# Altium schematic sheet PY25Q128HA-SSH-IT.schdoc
size 127 x 101 mm
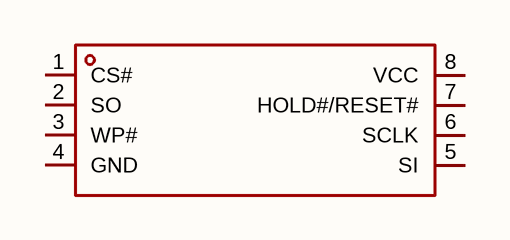
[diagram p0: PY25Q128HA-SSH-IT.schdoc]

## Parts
U?  py25q128ha-ssh-it  [SOP-8_L4.9-W3.9-P1.27-LS6.0-BL]  (value not drawn)

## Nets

Not connected (* = marked no-connect by the designer): U? 1(CS#) 2(SO) 3(WP#) 4(GND) 5(SI) 6(SCLK) 7(HOLD#/RESET#) 8(VCC)

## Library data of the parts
U? = py25q128ha-ssh-it: 接口类型:SPI;存储容量:128Mbit;时钟频率(fc):133MHz;; Manufacturer: PUYA(普冉); AddInBom: yes; ModelId: 75c24a7891ee4dd6bdac16a7163ff87e; ModelName: SOP-8_L4.9-W3.9-P1.27-LS6.0-BL-1; ModelTransform: 192.913,236.22,0,0,0,0,-0.393,2.749,0; Interface: SPI; Clock Frequency: 133MHz; Voltage - Supply: 2.7V~3.6V; Standby Supply Current: 15uA; Program / Erase Cycles: 100000次; Write Cycle Time (tWC): 12ms; Page Programming Time (Tpp): 500us; Block Erase Time(tBE): 800ms; Data Retention - TDR (Year): 20年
